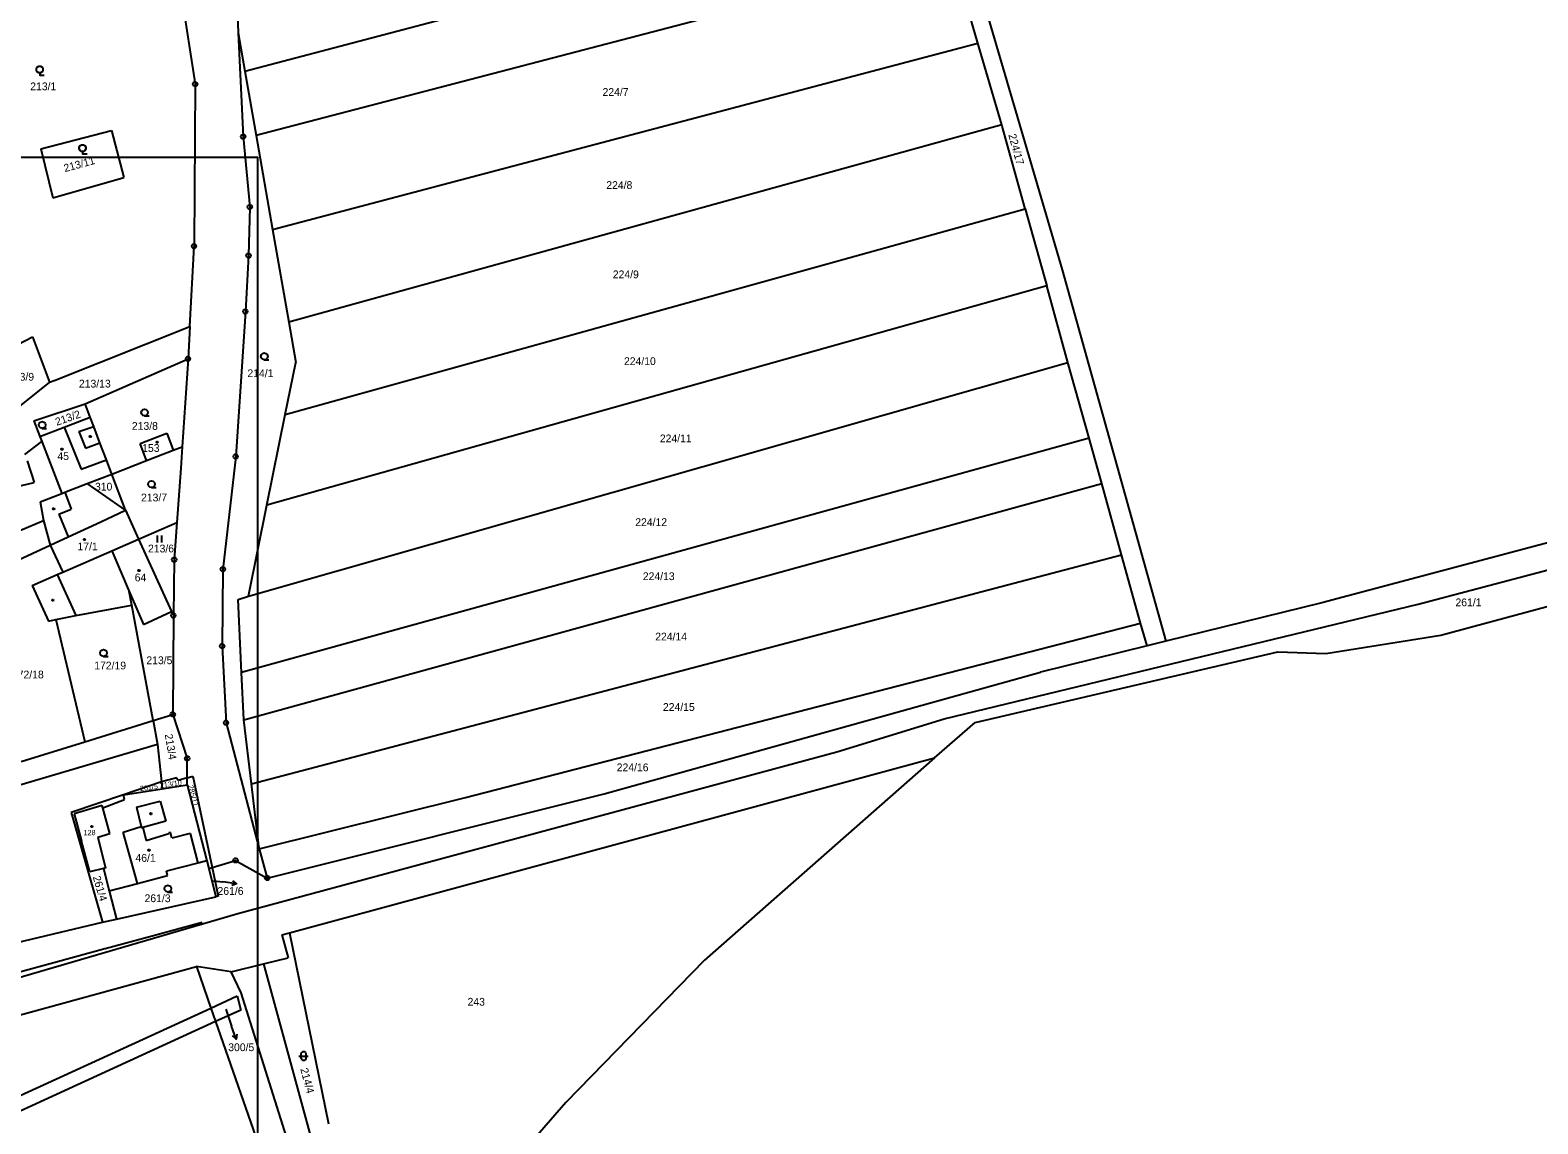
# Model space of a CAD drawing. Extents: x -779723 to -777378, y -1011169 to -1009297.
# Drawn here: x -778986.4 to -778656.8, y -1010479.3 to -1010240.1 of the extents above; entities that cross this region are included whole.
import ezdxf

# ---------------------------------------------------------------- set-up
doc = ezdxf.new("R2010")
doc.units = 0
for name, color, linetype in [('Default', 7, 'Continuous'), ('KN_HRANICE', 7, 'Continuous'), ('KN_KULTURY', 7, 'Continuous'), ('KN_PARCELY', 7, 'Continuous'), ('KN_SLUCKY', 7, 'Continuous'), ('KN_VEDENI', 7, 'Continuous'), ('LEGENDA', 7, 'Continuous'), ('Železniční svršek', 7, 'Continuous')]:
    doc.layers.add(name, color=color, linetype=linetype)

# ---------------------------------------------------------------- blocks, each defined once
blk = doc.blocks.new('304')
at = {"layer": 'Default'}
blk.add_lwpolyline([(0, 0), (-0.38, 0.1), (-0.65, 0.37), (-0.75, 0.74), (-0.65, 1.11), (-0.38, 1.38), (-0.01, 1.48), (0.36, 1.38), (0.63, 1.11), (0.73, 0.73), (0.63, 0.35), (0.36, 0.08), (-0.02, -0.02), (0.98, -0.02)], dxfattribs=at)
blk = doc.blocks.new('305')
at = {"layer": 'Default'}
blk.add_lwpolyline([(0, 0.53), (-0.19, 0.53), (-0.53, 0.72), (-0.72, 1.06), (-0.72, 1.45), (-0.53, 1.79), (-0.19, 1.98), (0.2, 1.98), (0.54, 1.79), (0.73, 1.45), (0.73, 1.06), (0.54, 0.72), (0.2, 0.53), (0.01, 0.53), (0.01, 0), (1.01, 0)], dxfattribs=at)
blk = doc.blocks.new('306')
at = {"layer": 'Default'}
for p, q in [((-0.5, 1.5), (-0.5, 0)), ((0.5, 0), (0.5, 1.5))]:
    blk.add_line(p, q, dxfattribs=at)
blk = doc.blocks.new('316')
at = {"layer": 'Default'}
for points in [[(-1, 1), (0.27, 1), (1, 1)], [(-0.5, 1.5), (-0.4, 1.79), (-0.15, 1.97), (0.16, 1.97), (0.41, 1.79), (0.51, 1.5), (0.51, 0.5), (0.41, 0.21), (0.16, 0.03), (-0.15, 0.03), (-0.4, 0.21), (-0.5, 0.5), (-0.5, 1.5)]]:
    blk.add_lwpolyline(points, dxfattribs=at)
blk = doc.blocks.new('10292')
at = {"layer": 'Default'}
blk.add_line((0, 3), (0, 0), dxfattribs=at)
blk.add_lwpolyline([(-0.5, 2), (0, 3), (0.5, 2)], dxfattribs=at)
blk = doc.blocks.new('402')
at = {"layer": 'Default'}
blk.add_lwpolyline([(0.09, 0.15), (0.18, 0), (0.09, -0.15), (-0.09, -0.15), (-0.18, 0), (-0.09, 0.15), (0.09, 0.15)], dxfattribs=at)
blk = doc.blocks.new('105')
at = {"layer": 'Default'}
blk.add_line((-0.12, 0), (0.12, 0), dxfattribs=at)
blk.add_lwpolyline([(0.15, 0.48), (0.4, 0.3), (0.5, 0.01), (0.4, -0.28), (0.15, -0.46), (-0.16, -0.46), (-0.41, -0.28), (-0.51, 0.01), (-0.41, 0.3), (-0.16, 0.48), (0.15, 0.48)], dxfattribs=at)

msp = doc.modelspace()

# ---------------------------------------------------------------- linework, layer by layer
at = {"layer": 'KN_HRANICE'}
for p, q in [((-778810.44, -1010123.41), (-778760.75, -1010292.49)), ((-778939.44, -1010249.05), (-778789, -1010209.36)), ((-778784.9, -1010223.38), (-778936.98, -1010263.15)), ((-778779.19, -1010242.93), (-778784.9, -1010223.38)), ((-778953.35, -1010232.46), (-778950.34, -1010251.89)), ((-778941.17, -1010234.88), (-778940.9, -1010240.67)), ((-778940.9, -1010240.67), (-778939.84, -1010263.37)), ((-778940.9, -1010240.67), (-778939.44, -1010249.05)), ((-778933.41, -1010283.65), (-778779.19, -1010242.93)), ((-778773.96, -1010260.81), (-778779.19, -1010242.93)), ((-778939.44, -1010249.05), (-778936.98, -1010263.15)), ((-778773.96, -1010260.81), (-778929.88, -1010303.92)), ((-778773.89, -1010261.06), (-778773.96, -1010260.81)), ((-778984.11, -1010266.01), (-778968.66, -1010262.03)), ((-778968.66, -1010262.03), (-778965.93, -1010272.29)), ((-778939.84, -1010263.37), (-778938.39, -1010278.77)), ((-778936.98, -1010263.15), (-778933.41, -1010283.65)), ((-778768.84, -1010279.18), (-778773.89, -1010261.06)), ((-778984.11, -1010266.01), (-778981.47, -1010276.78)), ((-778981.47, -1010276.78), (-778965.93, -1010272.29)), ((-778938.39, -1010278.77), (-778938.64, -1010289.39)), ((-778930.63, -1010324.14), (-778768.84, -1010279.18)), ((-778768.84, -1010279.18), (-778764.72, -1010293.95)), ((-778933.41, -1010283.65), (-778929.88, -1010303.92)), ((-778951.52, -1010304.9), (-778950.58, -1010287.37)), ((-778938.64, -1010289.39), (-778939.36, -1010301.65)), ((-778764.72, -1010293.95), (-778764.15, -1010296.01)), ((-778760.75, -1010292.49), (-778738.09, -1010373.73)), ((-778764.15, -1010296.01), (-778791.6, -1010303.74)), ((-778759.49, -1010312.74), (-778764.15, -1010296.01)), ((-778939.36, -1010301.65), (-778941.47, -1010333.34)), ((-778791.6, -1010303.74), (-778934.65, -1010344)), ((-778980.98, -1010316.61), (-778951.52, -1010304.9)), ((-778951.52, -1010304.9), (-778951.89, -1010311.98)), ((-778929.88, -1010303.92), (-778928.34, -1010312.81)), ((-778994.79, -1010311.83), (-778985.9, -1010307.16)), ((-778985.9, -1010307.16), (-778982.17, -1010317.08)), ((-778974.4, -1010321.81), (-778951.89, -1010311.98)), ((-778951.89, -1010311.98), (-778953.14, -1010331.19)), ((-778938.68, -1010363.9), (-778759.49, -1010312.74)), ((-778930.63, -1010324.14), (-778928.34, -1010312.81)), ((-778754.87, -1010329.33), (-778759.49, -1010312.74)), ((-778982.17, -1010317.08), (-778980.98, -1010316.61)), ((-778982.17, -1010317.08), (-778991.02, -1010324.17)), ((-778985.64, -1010325.53), (-778974.4, -1010321.81)), ((-778973.3, -1010324.71), (-778974.4, -1010321.81)), ((-778985.64, -1010325.53), (-778984.3, -1010328.99)), ((-778984.3, -1010328.99), (-778978.98, -1010326.92)), ((-778978.98, -1010326.92), (-778973.3, -1010324.71)), ((-778972.52, -1010326.77), (-778973.3, -1010324.71)), ((-778971.16, -1010330.34), (-778972.52, -1010326.77)), ((-778934.65, -1010344), (-778930.63, -1010324.14)), ((-778987.54, -1010332.88), (-778983.88, -1010330.06)), ((-778984.3, -1010328.99), (-778983.88, -1010330.06)), ((-778983.88, -1010330.06), (-778979.48, -1010341.4)), ((-778962.38, -1010330.47), (-778956.54, -1010328.23)), ((-778956.54, -1010328.23), (-778955.13, -1010331.96)), ((-778754.87, -1010329.33), (-778940.18, -1010380.55)), ((-778752.11, -1010339.25), (-778754.87, -1010329.33)), ((-778969.74, -1010334.07), (-778971.16, -1010330.34)), ((-778961.01, -1010334.24), (-778962.38, -1010330.47)), ((-778961.01, -1010334.24), (-778955.13, -1010331.96)), ((-778955.13, -1010331.96), (-778953.14, -1010331.19)), ((-778953.14, -1010331.19), (-778953.44, -1010335.87)), ((-778941.47, -1010333.34), (-778944.25, -1010358.02)), ((-778968.56, -1010337.17), (-778969.74, -1010334.07)), ((-778968.56, -1010337.17), (-778961.01, -1010334.24)), ((-778953.44, -1010335.87), (-778954.32, -1010347.77)), ((-778977.19, -1010340.51), (-778973.94, -1010339.25)), ((-778973.94, -1010339.25), (-778968.56, -1010337.17)), ((-778965.56, -1010345.08), (-778973.94, -1010339.25)), ((-778965.56, -1010345.08), (-778968.56, -1010337.17)), ((-778939.67, -1010390.9), (-778752.11, -1010339.25)), ((-778747.77, -1010354.85), (-778752.11, -1010339.25)), ((-778984.19, -1010343.23), (-778979.48, -1010341.4)), ((-778984.19, -1010343.23), (-778983.47, -1010347.31)), ((-778979.48, -1010341.4), (-778978.84, -1010341.15)), ((-778978.84, -1010341.15), (-778977.19, -1010340.51)), ((-778965.56, -1010345.08), (-778962.69, -1010351.41)), ((-778938.68, -1010363.9), (-778934.65, -1010344)), ((-778983.47, -1010347.31), (-778982.04, -1010352.73)), ((-778962.69, -1010351.41), (-778954.32, -1010347.77)), ((-778954.32, -1010347.77), (-778954.92, -1010355.9)), ((-778997.87, -1010360.08), (-778982.04, -1010352.73)), ((-778982.04, -1010352.73), (-778979.24, -1010358.61)), ((-778967.89, -1010353.67), (-778962.69, -1010351.41)), ((-778962.69, -1010351.41), (-778955.49, -1010367.27)), ((-778650.77, -1010351.2), (-778703.98, -1010365.37)), ((-778979.24, -1010358.61), (-778968.59, -1010353.97)), ((-778968.59, -1010353.97), (-778967.89, -1010353.67)), ((-778954.92, -1010355.9), (-778955.1, -1010368.13)), ((-778937.98, -1010404.92), (-778747.77, -1010354.85)), ((-778743.6, -1010369.82), (-778747.77, -1010354.85)), ((-778985.96, -1010361.53), (-778980.51, -1010359.16)), ((-778980.51, -1010359.16), (-778979.24, -1010358.61)), ((-778944.25, -1010358.02), (-778944.43, -1010374.8)), ((-778985.96, -1010361.53), (-778982.41, -1010369.32)), ((-778964.75, -1010362.86), (-778961.63, -1010370.1)), ((-778964.2, -1010365.84), (-778964.75, -1010362.86)), ((-778976.43, -1010368.12), (-778964.2, -1010365.84)), ((-778959.52, -1010391.1), (-778964.2, -1010365.84)), ((-778940.96, -1010364.6), (-778938.68, -1010363.9)), ((-778940.18, -1010380.55), (-778940.96, -1010364.6)), ((-778703.98, -1010365.37), (-778738.09, -1010373.73)), ((-778678, -1010372.43), (-778652.28, -1010365.5)), ((-778982.41, -1010369.32), (-778980.82, -1010369)), ((-778980.82, -1010369), (-778976.43, -1010368.12)), ((-778980.82, -1010369), (-778974.46, -1010395.73)), ((-778961.63, -1010370.1), (-778955.49, -1010367.27)), ((-778955.49, -1010367.27), (-778955.1, -1010368.13)), ((-778955.1, -1010368.13), (-778955.22, -1010389.77)), ((-778891.25, -1010407.94), (-778743.6, -1010369.82)), ((-778742.19, -1010374.76), (-778743.6, -1010369.82)), ((-778703.11, -1010376.44), (-778678, -1010372.43)), ((-778944.43, -1010374.8), (-778943.59, -1010391.58)), ((-778779.77, -1010391.5), (-778713.61, -1010376.07)), ((-778742.19, -1010374.76), (-778765.47, -1010380.48)), ((-778738.09, -1010373.73), (-778742.19, -1010374.76)), ((-778713.61, -1010376.07), (-778703.11, -1010376.44)), ((-778939.67, -1010390.9), (-778940.18, -1010380.55)), ((-778860.91, -1010407.13), (-778765.47, -1010380.48)), ((-778974.46, -1010395.73), (-778959.52, -1010391.1)), ((-778959.52, -1010391.1), (-778955.22, -1010389.77)), ((-778959.52, -1010391.1), (-778958.54, -1010396.31)), ((-778955.22, -1010389.77), (-778952.07, -1010399.39)), ((-778943.59, -1010391.58), (-778936.31, -1010419.18)), ((-778937.98, -1010404.92), (-778939.67, -1010390.9)), ((-778788.69, -1010399.25), (-778779.77, -1010391.5)), ((-778988.37, -1010400.03), (-778974.46, -1010395.73)), ((-778958.54, -1010396.31), (-779043.02, -1010421.24)), ((-778958.54, -1010396.31), (-778957.7, -1010404.52)), ((-778952.08, -1010403.6), (-778952.07, -1010399.39)), ((-778929.7, -1010437.49), (-778788.69, -1010399.25)), ((-778788.69, -1010399.25), (-778838.99, -1010443.52)), ((-778957.7, -1010404.52), (-778966, -1010407.32)), ((-778966, -1010407.32), (-778957.55, -1010406.02)), ((-778954.34, -1010403.64), (-778957.7, -1010404.52)), ((-778957.7, -1010404.52), (-778957.55, -1010406.02)), ((-778957.55, -1010406.02), (-778952.09, -1010405.18)), ((-778954.03, -1010404.17), (-778954.34, -1010403.64)), ((-778952.08, -1010403.6), (-778954.03, -1010404.17)), ((-778952.09, -1010405.18), (-778952.08, -1010403.6)), ((-778952.09, -1010405.18), (-778947.8, -1010421.79)), ((-778952.08, -1010403.6), (-778950.86, -1010403.24)), ((-778950.86, -1010403.24), (-778946.64, -1010423.24)), ((-778936.31, -1010419.18), (-778937.98, -1010404.92)), ((-778966, -1010407.32), (-778977.43, -1010411.17)), ((-778970.52, -1010410.2), (-778965.76, -1010408.34)), ((-778965.76, -1010408.34), (-778966, -1010407.32)), ((-778936.31, -1010419.18), (-778891.25, -1010407.94)), ((-778934.57, -1010425.53), (-778860.91, -1010407.13)), ((-778977.43, -1010411.17), (-778970.59, -1010435.19)), ((-778970.66, -1010409.66), (-778976.79, -1010411.48)), ((-778976.79, -1010411.48), (-778975.16, -1010417.48)), ((-778970.52, -1010410.2), (-778970.66, -1010409.66)), ((-778968.98, -1010415.79), (-778970.52, -1010410.2)), ((-778971.61, -1010416.57), (-778968.98, -1010415.79)), ((-778973.38, -1010424.16), (-778975.16, -1010417.48)), ((-778971.61, -1010416.57), (-778969.93, -1010423.36)), ((-778936.31, -1010419.18), (-778934.57, -1010425.53)), ((-778949.74, -1010422.28), (-778956.63, -1010424.04)), ((-778947.8, -1010421.79), (-778949.74, -1010422.28)), ((-778947.8, -1010421.79), (-778947.37, -1010423.47)), ((-778946.64, -1010423.24), (-778941.48, -1010421.68)), ((-778941.48, -1010421.68), (-778934.57, -1010425.53)), ((-778970.41, -1010423.47), (-778973.38, -1010424.16)), ((-778969.93, -1010423.36), (-778970.41, -1010423.47)), ((-778970.41, -1010423.47), (-778969.13, -1010428.34)), ((-778962.94, -1010426.72), (-778956.41, -1010425.01)), ((-778956.41, -1010425.01), (-778956.63, -1010424.04)), ((-778947.37, -1010423.47), (-778946.64, -1010423.24)), ((-778947.37, -1010423.47), (-778945.78, -1010429.62)), ((-778946.64, -1010423.24), (-778945.31, -1010429.51)), ((-778969.13, -1010428.34), (-778962.94, -1010426.72)), ((-778969.13, -1010428.34), (-778967.51, -1010434.5)), ((-778967.51, -1010434.5), (-778945.78, -1010429.62)), ((-778945.31, -1010429.51), (-778945.78, -1010429.62)), ((-779030.17, -1010449.35), (-778970.59, -1010435.19)), ((-778970.59, -1010435.19), (-778967.51, -1010434.5)), ((-778931.37, -1010437.94), (-778929.7, -1010437.49)), ((-778931.37, -1010437.94), (-778930.03, -1010442.98)), ((-778929.7, -1010437.49), (-778921.17, -1010479.33)), ((-779027.37, -1010466.13), (-778950.06, -1010444.91)), ((-778942.45, -1010446.06), (-778950.06, -1010444.91)), ((-778950.06, -1010444.91), (-778946.9, -1010453.97)), ((-778942.45, -1010446.06), (-778935.36, -1010444.3)), ((-778935.36, -1010444.3), (-778930.03, -1010442.98)), ((-778935.36, -1010444.3), (-778923.56, -1010487.7)), ((-778838.99, -1010443.52), (-778869.31, -1010474.62)), ((-778940.29, -1010450.68), (-778942.45, -1010446.06)), ((-778946.9, -1010453.97), (-778941.12, -1010451.33)), ((-778941.12, -1010451.33), (-778940.34, -1010454.4)), ((-778929.57, -1010484.72), (-778940.29, -1010450.68)), ((-778990.37, -1010473.89), (-778946.9, -1010453.97)), ((-778946.9, -1010453.97), (-778945.86, -1010456.94)), ((-778940.34, -1010454.4), (-778945.86, -1010456.94)), ((-778945.86, -1010456.94), (-778990.5, -1010477.42)), ((-778945.86, -1010456.94), (-778927.24, -1010510.3)), ((-778869.31, -1010474.62), (-778908.34, -1010519.61))]:
    msp.add_line(p, q, dxfattribs=at)
msp.add_lwpolyline([(-778950.34, -1010251.89), (-778950.58, -1010286.9), (-778950.58, -1010287.37)], dxfattribs=at)
at = {"layer": 'KN_PARCELY'}
for p, q in [((-778946.3, -1010426.12), (-778944.25, -1010426.4)), ((-778943.64, -1010454.24), (-778942.37, -1010457.97))]:
    msp.add_line(p, q, dxfattribs=at)
at = {"layer": 'KN_SLUCKY'}
for p, q in [((-778978.98, -1010326.92), (-778975.29, -1010336.14)), ((-778975.77, -1010327.87), (-778972.52, -1010326.77)), ((-778975.77, -1010327.87), (-778974.32, -1010331.52)), ((-778974.32, -1010331.52), (-778971.16, -1010330.34)), ((-778987.09, -1010334.27), (-778985.56, -1010339)), ((-778975.29, -1010336.14), (-778969.74, -1010334.07)), ((-778996.79, -1010341.72), (-778985.56, -1010339)), ((-778978.84, -1010341.15), (-778977.42, -1010344.84)), ((-778980.14, -1010345.98), (-778977.42, -1010344.84)), ((-778980.14, -1010345.98), (-778978.1, -1010350.9)), ((-778970.99, -1010347.6), (-778965.56, -1010345.08)), ((-779000.55, -1010354.53), (-778983.47, -1010347.31)), ((-778978.1, -1010350.9), (-778970.99, -1010347.6)), ((-778982.04, -1010352.73), (-778978.1, -1010350.9)), ((-778968.59, -1010353.97), (-778964.75, -1010362.86)), ((-778980.51, -1010359.16), (-778976.43, -1010368.12)), ((-778963.18, -1010410.04), (-778957.95, -1010408.71)), ((-778957.95, -1010408.71), (-778956.78, -1010413.11)), ((-778963.18, -1010410.04), (-778962.15, -1010414.29)), ((-778966.1, -1010415.49), (-778962.15, -1010414.29)), ((-778962.94, -1010426.72), (-778966.1, -1010415.49)), ((-778962.15, -1010414.29), (-778962.09, -1010414.54)), ((-778962.09, -1010414.54), (-778961.8, -1010414.46)), ((-778956.78, -1010413.11), (-778961.8, -1010414.46)), ((-778961.8, -1010414.46), (-778961.07, -1010417.35)), ((-778961.07, -1010417.35), (-778956.08, -1010415.8)), ((-778955.71, -1010415.59), (-778956.1, -1010415.63)), ((-778956.1, -1010415.63), (-778956.08, -1010415.8)), ((-778955.41, -1010416.79), (-778955.71, -1010415.59)), ((-778951.46, -1010415.8), (-778955.41, -1010416.79)), ((-778951.46, -1010415.8), (-778949.74, -1010422.28))]:
    msp.add_line(p, q, dxfattribs=at)
at = {"layer": 'KN_VEDENI'}
for p, q in [((-778682.94, -1010365.64), (-778610.59, -1010346.52)), ((-778786.59, -1010390.75), (-778682.94, -1010365.64)), ((-778810.01, -1010397.92), (-778786.59, -1010390.75)), ((-778940.99, -1010433.26), (-778810.01, -1010397.92)), ((-779042.85, -1010463.08), (-778940.99, -1010433.26))]:
    msp.add_line(p, q, dxfattribs=at)
at = {"layer": 'LEGENDA'}
msp.add_lwpolyline([(-779530.66, -1010687.91), (-778936.66, -1010687.91), (-778936.66, -1010267.91), (-779530.66, -1010267.91)], close=True, dxfattribs=at)
at = {"layer": 'Železniční svršek'}
for points in [[(-778948.81, -1010435.26), (-778959.77, -1010438.24)], [(-778959.77, -1010438.25), (-778970.04, -1010441.03)], [(-778970.05, -1010441.03), (-778980.42, -1010443.86)], [(-778980.43, -1010443.86), (-778990.86, -1010446.68)]]:
    msp.add_lwpolyline(points, dxfattribs=at)
for centre, start, end in [((-778960.03, -1010437.28), 285.1631, 285.241), ((-778969.78, -1010441.99), 105.1631, 105.2607), ((-778980.69, -1010442.9), 285.1366, 285.2607)]:
    msp.add_arc(centre, 1, start, end, dxfattribs=at)

# ---------------------------------------------------------------- block references
at = {"layer": 'KN_KULTURY'}
for name, p in [('305', (-778984.34, -1010249.95)), ('305', (-778974.98, -1010267.13)), ('304', (-778935.21, -1010312.17)), ('304', (-778961.38, -1010324.45)), ('304', (-778983.79, -1010327.17)), ('402', (-778973.25, -1010328.93)), ('402', (-778958.66, -1010330.2)), ('402', (-778979.46, -1010331.7)), ('304', (-778959.86, -1010340.11)), ('402', (-778981.27, -1010344.78)), ('402', (-778974.54, -1010351.5)), ('306', (-778958.14, -1010352.14)), ('402', (-778962.61, -1010358.29)), ('402', (-778981.46, -1010364.79)), ('304', (-778970.35, -1010377.05)), ('402', (-778960.04, -1010411.46)), ('402', (-778972.93, -1010414.29)), ('402', (-778960.42, -1010419.46)), ('304', (-778956.29, -1010428.59)), ('316', (-778926.63, -1010465.47))]:
    msp.add_blockref(name, p, dxfattribs=at)
at = {"layer": 'KN_PARCELY'}
for p in [(-778950.34, -1010251.89), (-778939.84, -1010263.37), (-778938.39, -1010278.77), (-778950.58, -1010287.37), (-778938.64, -1010289.39), (-778939.36, -1010301.65), (-778951.89, -1010311.98), (-778941.47, -1010333.34), (-778954.92, -1010355.9), (-778944.25, -1010358.02), (-778955.1, -1010368.13), (-778944.43, -1010374.8), (-778955.22, -1010389.77), (-778943.59, -1010391.58), (-778952.07, -1010399.39), (-778941.48, -1010421.68), (-778934.57, -1010425.53)]:
    msp.add_blockref('105', p, dxfattribs=at)
for p, rotation in [((-778944.25, -1010426.4), -97.64262599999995), ((-778942.37, -1010457.97), -161.183645)]:
    msp.add_blockref('10292', p, dxfattribs=dict(at, rotation=rotation))

# ---------------------------------------------------------------- texts
for s, height, p in [('213/1', 1.7, (-778986.39, -1010253.23)), ('224/7', 1.7, (-778861.26, -1010254.46)), ('224/8', 1.7, (-778860.44, -1010274.82)), ('224/9', 1.7, (-778859.02, -1010294.35)), ('224/10', 1.7, (-778856.57, -1010313.33)), ('213/9', 1.7, (-778991.25, -1010316.75)), ('213/13', 1.7, (-778975.75, -1010318.25)), ('214/1', 1.7, (-778938.91, -1010315.98)), ('213/8', 1.7, (-778964.17, -1010327.5)), ('224/11', 1.7, (-778848.73, -1010330.23)), ('45', 1.7, (-778980.46, -1010334.11)), ('153', 1.7, (-778961.92, -1010332.33)), ('310', 1.7, (-778972.24, -1010340.78)), ('213/7', 1.7, (-778962.16, -1010343.15)), ('224/12', 1.7, (-778854.1, -1010348.54)), ('17/1', 1.7, (-778976.06, -1010353.85)), ('213/6', 1.7, (-778960.64, -1010354.31)), ('64', 1.7, (-778963.55, -1010360.64)), ('224/13', 1.7, (-778852.45, -1010360.37)), ('261/1', 1.7, (-778674.77, -1010366.09)), ('224/14', 1.7, (-778849.74, -1010373.58)), ('172/19', 1.7, (-778972.4, -1010379.9)), ('213/5', 1.7, (-778961, -1010378.76)), ('172/18', 1.7, (-778990.39, -1010381.87)), ('224/15', 1.7, (-778848.05, -1010388.98)), ('224/16', 1.7, (-778858.16, -1010402.18)), ('128', 1.14, (-778974.74, -1010416.16)), ('46/1', 1.7, (-778963.39, -1010421.98)), ('261/3', 1.7, (-778961.4, -1010430.81)), ('261/6', 0.1, (-778946.54, -1010426.12)), ('261/6', 1.7, (-778945.45, -1010429.21)), ('243', 1.7, (-778890.77, -1010453.45)), ('300/5', 0.1, (-778943.63, -1010454.24)), ('300/5', 1.7, (-778943.1, -1010463.4))]:
    msp.add_text(s, height=height, dxfattribs=at).set_placement(p)
for s, height, rotation, p in [('224/17', 1.7, 285.562, (-778772.55, -1010263.01)), ('213/11', 1.7, 15.298, (-778978.81, -1010271.15)), ('213/2', 1.7, 19.309, (-778980.58, -1010326.63)), ('213/4', 1.7, 279.374, (-778956.98, -1010394.15)), ('261/5', 1.14, 7.964, (-778962.33, -1010406.55)), ('213/10', 1.14, 7.62, (-778957.97, -1010405.86)), ('285/11', 1.14, 284.932, (-778951.91, -1010405.34)), ('261/4', 1.7, 286.364, (-778972.74, -1010425.31)), ('214/4', 1.7, 285.047, (-778927.36, -1010467.32))]:
    msp.add_text(s, height=height, rotation=rotation, dxfattribs=at).set_placement(p)

doc.saveas('drawing.dxf')
